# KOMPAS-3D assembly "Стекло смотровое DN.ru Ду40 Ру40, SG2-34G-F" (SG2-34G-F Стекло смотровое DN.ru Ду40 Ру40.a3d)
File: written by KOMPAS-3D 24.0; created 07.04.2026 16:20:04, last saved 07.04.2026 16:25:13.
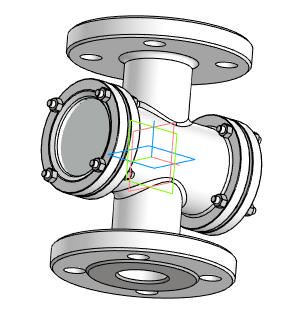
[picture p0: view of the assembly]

Document properties: Автор: Main; Полное имя файла: D:\DN.ru Аутсерс\Стекло смотровое DN.ru\Исходники\Стекло смотровое DN.ru SG2-34G-F тип В ГОСТ 21836-2021 Ду40 Ру40, углеродистая сталь, фланцевое\SG2-34G-F Стекло смотровое DN.ru Ду40 Ру40.a3d

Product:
- Component [detail]: Деталь  | qty 1  | pos. 1  | Масса: 7.155643; Автор: Main; additional columns: Типовые; source file: ДетальДеталь.m3d
- Component [detail]: Стекло  | qty 2  | pos. 2  | Масса: 0.138488; Автор: Main; source file: СтеклоСтекло.m3d
- Component [detail]: ANSI B18.2.4.2M - M6x1 - 10  | designation ANSI B18.2.4.2M - M6x1  | qty 16  | pos. 3  | Масса: 0.003008; Комментарий: Типы метрических   шестигранных гаек   2; Автор: Main; additional columns: Сталь, мягкая; source file: ANSI B18.2.4.2M - M6x1ANSI B18.2.4.2M - M6x1 - 10.m3d
- Part/product: Стекло смотровое DN.ru Ду40 Ру40  | designation SG2-34G-F
    Масса: 9
    Раздел спецификации: Прочие изделия
    Примечание: D500-00083

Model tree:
1. Массив по концентрической сетке:1  (labels: Грань.Твердое тело1; Ребро.Твердое тело1; Ребро.Solid1; Грань.Solid1)  (4 pattern instances)
     Шаг 2 = 360

Expressions: SG2-34G-F
Referenced files in D:\DN.ru Аутсерс\Стекло смотровое DN.ru\Исходники\Стекло смотровое DN.ru SG2-34G-F тип В ГОСТ 21836-2021 Ду40 Ру40, углеродистая сталь, фланцевое\: ДетальДеталь.m3d, СтеклоСтекло.m3d, ANSI B18.2.4.2M - M6x1ANSI B18.2.4.2M - M6x1 - 10.m3d
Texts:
  Стекло Стекло (1)
  Стекло Стекло (2)
  ANSI B18.2.4.2M - M6x1 ANSI B18.2.4.2M - M6x1 - 10 (1)
  ANSI B18.2.4.2M - M6x1 ANSI B18.2.4.2M - M6x1 - 10 (2)
  ANSI B18.2.4.2M - M6x1 ANSI B18.2.4.2M - M6x1 - 10 (3)
  ANSI B18.2.4.2M - M6x1 ANSI B18.2.4.2M - M6x1 - 10 (4)
  ANSI B18.2.4.2M - M6x1 ANSI B18.2.4.2M - M6x1 - 10 (5)
  ANSI B18.2.4.2M - M6x1 ANSI B18.2.4.2M - M6x1 - 10 (6)
  ANSI B18.2.4.2M - M6x1 ANSI B18.2.4.2M - M6x1 - 10 (7)
  ANSI B18.2.4.2M - M6x1 ANSI B18.2.4.2M - M6x1 - 10 (8)
  ANSI B18.2.4.2M - M6x1 ANSI B18.2.4.2M - M6x1 - 10 (9)
  ANSI B18.2.4.2M - M6x1 ANSI B18.2.4.2M - M6x1 - 10 (10)
  ANSI B18.2.4.2M - M6x1 ANSI B18.2.4.2M - M6x1 - 10 (11)
  ANSI B18.2.4.2M - M6x1 ANSI B18.2.4.2M - M6x1 - 10 (12)
  ANSI B18.2.4.2M - M6x1 ANSI B18.2.4.2M - M6x1 - 10 (13)
  ANSI B18.2.4.2M - M6x1 ANSI B18.2.4.2M - M6x1 - 10 (14)
  ANSI B18.2.4.2M - M6x1 ANSI B18.2.4.2M - M6x1 - 10 (15)
  ANSI B18.2.4.2M - M6x1 ANSI B18.2.4.2M - M6x1 - 10 (16)
  Ось Z.Начало координат
  Ось X.Начало координат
